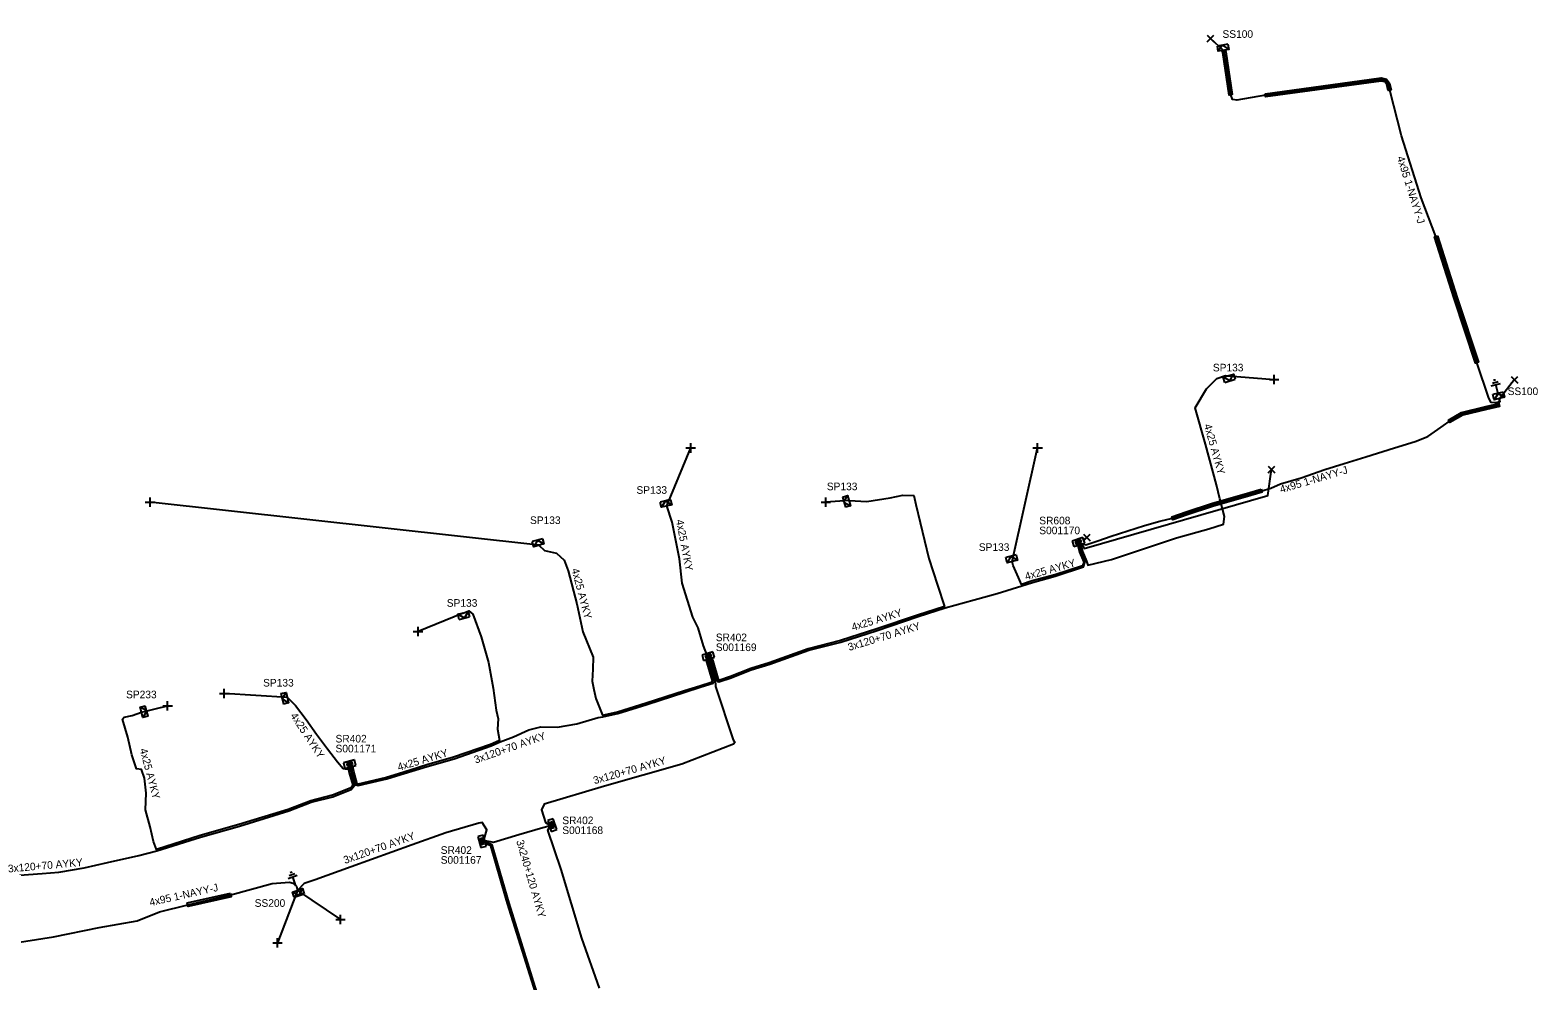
# Model space of a CAD drawing. Extents: x -763093 to -760976, y -1155572 to -1152009.
# Drawn here: x -761448.7 to -761250.7, y -1152363.9 to -1152239 of the extents above; entities that cross this region are included whole.
import ezdxf

# ---------------------------------------------------------------- set-up
doc = ezdxf.new("R2010")
doc.units = 0
for name, color, linetype in [('Vrstva 1', 7, 'Continuous'), ('Vrstva 14', 7, 'Continuous'), ('Vrstva 15', 7, 'Continuous'), ('Vrstva 20', 7, 'Continuous'), ('Vrstva 28', 7, 'Continuous'), ('Vrstva 29', 7, 'Continuous'), ('Vrstva 30', 7, 'Continuous'), ('Vrstva 31', 7, 'Continuous'), ('Vrstva 33', 7, 'Continuous'), ('Vrstva 34', 7, 'Continuous'), ('Vrstva 5', 7, 'Continuous'), ('Vrstva 59', 7, 'Continuous'), ('Vrstva 6', 7, 'Continuous'), ('Vrstva 8', 7, 'Continuous'), ('Vrstva 9', 7, 'Continuous')]:
    doc.layers.add(name, color=color, linetype=linetype)

# ---------------------------------------------------------------- blocks, each defined once
blk = doc.blocks.new('NN800')
at = {"layer": 'Vrstva 1'}
for points in [[(-0.44, 0.44), (0.44, -0.44)], [(-0.44, -0.44), (0.44, 0.44)]]:
    blk.add_lwpolyline(points, dxfattribs=at)
blk = doc.blocks.new('NN620')
at = {"layer": 'Vrstva 8'}
for points in [[(0.75, 0), (-0.75, 0)], [(-0.75, 0), (-0.75, -0.75)], [(0.75, -0.75), (0.75, 0)], [(-0.75, -0.75), (0.75, -0.75)], [(0.37, -0.18), (-0.38, -0.18)], [(-0.38, -0.18), (-0.38, -0.56)], [(-0.38, -0.56), (0.37, -0.56)], [(0.32, -0.23), (-0.33, -0.23)], [(-0.33, -0.23), (-0.33, -0.51)], [(-0.33, -0.51), (0.32, -0.51)], [(0.27, -0.27), (-0.28, -0.27)], [(-0.28, -0.27), (-0.28, -0.46)], [(-0.28, -0.46), (0.27, -0.46)], [(0.23, -0.32), (-0.23, -0.32)], [(-0.23, -0.32), (-0.23, -0.42)], [(-0.23, -0.42), (0.23, -0.42)], [(-0.19, -0.37), (0.19, -0.37)], [(0.23, -0.42), (0.23, -0.32)], [(0.27, -0.46), (0.27, -0.27)], [(0.32, -0.51), (0.32, -0.23)], [(0.37, -0.56), (0.37, -0.18)]]:
    blk.add_lwpolyline(points, dxfattribs=at)
blk = doc.blocks.new('NN630')
at = {"layer": 'Vrstva 9'}
for points in [[(0, -0.7), (-0.7, 0)], [(-0.7, -0.7), (-0.7, 0), (0.7, 0), (0.7, -0.7)], [(-0.7, -0.7), (0.7, -0.7)], [(0, -0.7), (0.7, 0)]]:
    blk.add_lwpolyline(points, dxfattribs=at)
blk = doc.blocks.new('NN810')
at = {"layer": 'Vrstva 14'}
for points in [[(0.63, -1.89), (-0.62, -1.89)], [(0, -0.64), (0, -1.89)], [(0.39, -2.2), (-0.4, -2.2)], [(0, -2.52), (-0.12, -2.52)], [(0.14, -2.52), (0, -2.52)]]:
    blk.add_lwpolyline(points, dxfattribs=at)

msp = doc.modelspace()

# ---------------------------------------------------------------- linework, layer by layer
at = {"layer": 'Vrstva 20'}
for points in [[(-761291.83, -1152241.57), (-761291.74, -1152241.82), (-761290.87, -1152247.46), (-761291.27, -1152247.52), (-761292.12, -1152241.92), (-761292.21, -1152241.71)], [(-761286.56, -1152247.35), (-761271.31, -1152245.27), (-761270.6, -1152245.43), (-761270.23, -1152245.96), (-761270.01, -1152246.81), (-761270.39, -1152246.91), (-761270.59, -1152246.14), (-761270.84, -1152245.79), (-761271.33, -1152245.67), (-761286.5, -1152247.75)], [(-761263.93, -1152266.03), (-761261.36, -1152274.14), (-761258.55, -1152282.6), (-761258.93, -1152282.72), (-761261.74, -1152274.26), (-761264.31, -1152266.15)], [(-761255.85, -1152288.05), (-761255.77, -1152288.45), (-761257.48, -1152288.83), (-761260.61, -1152289.58), (-761262.28, -1152290.55), (-761262.48, -1152290.21), (-761260.77, -1152289.2), (-761257.58, -1152288.45)], [(-761287.06, -1152299.3), (-761286.94, -1152299.68), (-761288.43, -1152300.12), (-761293.49, -1152301.57), (-761296.81, -1152302.65), (-761298.67, -1152303.31), (-761298.81, -1152302.93), (-761296.93, -1152302.27), (-761293.61, -1152301.19), (-761288.55, -1152299.74)], [(-761422.44, -1152352.36), (-761422.33, -1152352.84), (-761428.01, -1152354.12), (-761428.11, -1152353.64)]]:
    msp.add_lwpolyline(points, close=True, dxfattribs=at)
at = {"layer": 'Vrstva 5'}
for points in [[(-761255.79, -1152287.38), (-761255.77, -1152287.54), (-761255.75, -1152287.82), (-761256.36, -1152287.95), (-761256.87, -1152287.91), (-761257.18, -1152287.35), (-761258.74, -1152282.66), (-761261.55, -1152274.2), (-761264.12, -1152266.09), (-761266.07, -1152261.03), (-761268.63, -1152252.86), (-761270.2, -1152246.86), (-761270.41, -1152246.05), (-761270.72, -1152245.61), (-761271.32, -1152245.47), (-761286.53, -1152247.55), (-761290.28, -1152248.19), (-761290.86, -1152248.1), (-761291.07, -1152247.49), (-761291.93, -1152241.87), (-761292.02, -1152241.64)], [(-761310.78, -1152306.54), (-761310.56, -1152307.46), (-761310.01, -1152308.73), (-761309.83, -1152309.27), (-761306.73, -1152308.52), (-761300.15, -1152306.34), (-761298.2, -1152305.67), (-761293.96, -1152304.5), (-761292.04, -1152303.87), (-761291.91, -1152302.86), (-761292.49, -1152300.56), (-761292.94, -1152298.7), (-761294.39, -1152293.4), (-761295.74, -1152288.61), (-761294.24, -1152286.09), (-761292.9, -1152284.74), (-761291.75, -1152284.37), (-761291.38, -1152284.39)], [(-761310.47, -1152306.43), (-761310.12, -1152306.61), (-761308.54, -1152306.08), (-761306.77, -1152305.47), (-761302.39, -1152304.08), (-761300.39, -1152303.51), (-761298.74, -1152303.12), (-761296.87, -1152302.46), (-761293.55, -1152301.38), (-761288.49, -1152299.93), (-761287, -1152299.49), (-761285.83, -1152299.14), (-761284.53, -1152298.61), (-761281.84, -1152297.81), (-761278.73, -1152296.72), (-761276.18, -1152295.93), (-761273.33, -1152295.04), (-761269.56, -1152293.88), (-761266.84, -1152293.02), (-761265.18, -1152292.38), (-761263.87, -1152291.43), (-761262.38, -1152290.38), (-761260.69, -1152289.39), (-761257.53, -1152288.64), (-761255.81, -1152288.25), (-761255.79, -1152287.38)], [(-761341.2, -1152300.8), (-761338.88, -1152300.9), (-761335.82, -1152300.44), (-761334.13, -1152300.1), (-761332.68, -1152300.11), (-761332.41, -1152301.32), (-761330.71, -1152308.4), (-761329.6, -1152311.91), (-761328.66, -1152314.71), (-761332.2, -1152315.85), (-761337.55, -1152317.66), (-761342.33, -1152319.17), (-761346.56, -1152320.26), (-761351.68, -1152322.1), (-761354.1, -1152322.86), (-761356.75, -1152323.91), (-761358.32, -1152324.41), (-761359.06, -1152321.83), (-761359.21, -1152321.45)], [(-761359.89, -1152320.99), (-761360.32, -1152319.86), (-761361, -1152317.5), (-761361.71, -1152316.09), (-761363.12, -1152311.66), (-761363.46, -1152308.43), (-761364.44, -1152303.61), (-761365.14, -1152301.5)], [(-761381.94, -1152306.66), (-761381.21, -1152307.36), (-761379.64, -1152307.7), (-761378.61, -1152308.62), (-761378.09, -1152310.04), (-761376.96, -1152314.37), (-761376.15, -1152318.03), (-761374.8, -1152321.38), (-761374.86, -1152322.92), (-761374.93, -1152324.53), (-761374.74, -1152325.63), (-761374.45, -1152326.8), (-761373.59, -1152328.99), (-761371.6, -1152328.56), (-761367.83, -1152327.38), (-761362.82, -1152325.75), (-761360.82, -1152325.11), (-761359.2, -1152324.6), (-761359.13, -1152324.47), (-761359.82, -1152322.09), (-761359.95, -1152321.73)], [(-761359.39, -1152321.52), (-761359.25, -1152321.9), (-761358.48, -1152324.57), (-761358.31, -1152324.62), (-761356.69, -1152324.09), (-761354.04, -1152323.04), (-761351.62, -1152322.29), (-761346.5, -1152320.46), (-761342.27, -1152319.37), (-761337.49, -1152317.84), (-761332.14, -1152316.04), (-761328.6, -1152314.9), (-761324.75, -1152313.83), (-761321.73, -1152312.99), (-761318.49, -1152312.01), (-761317.09, -1152311.55), (-761314.13, -1152310.74), (-761310.4, -1152309.51), (-761310.19, -1152308.81), (-761310.75, -1152307.52), (-761310.97, -1152306.6)], [(-761311.17, -1152306.65), (-761310.94, -1152307.58), (-761310.37, -1152308.89), (-761310.54, -1152309.35), (-761314.19, -1152310.54), (-761317.15, -1152311.35), (-761318.56, -1152311.82), (-761318.93, -1152310.9), (-761319.63, -1152309.31), (-761319.76, -1152308.78)], [(-761391.89, -1152315.56), (-761391.13, -1152315.27), (-761390.59, -1152315.71), (-761389.5, -1152318.67), (-761388.54, -1152322.07), (-761387.92, -1152325.45), (-761387.56, -1152328.31), (-761387.29, -1152329.46), (-761387.39, -1152330.81), (-761387.1, -1152332.3), (-761388.3, -1152332.85), (-761393.14, -1152334.52), (-761396.65, -1152335.51), (-761399.68, -1152336.47), (-761401.95, -1152337.16), (-761405.66, -1152338.04), (-761405.82, -1152337.99), (-761406.25, -1152336.4), (-761406.39, -1152335.69)], [(-761406.58, -1152335.75), (-761406.44, -1152336.45), (-761405.99, -1152338.15), (-761405.66, -1152338.24), (-761401.89, -1152337.36), (-761399.62, -1152336.66), (-761396.59, -1152335.71), (-761393.08, -1152334.71), (-761388.22, -1152333.03), (-761387.04, -1152332.49), (-761385.26, -1152331.81), (-761383.26, -1152330.92), (-761381.67, -1152330.52), (-761379.47, -1152330.55), (-761376.93, -1152330.12), (-761374.15, -1152329.28), (-761373.53, -1152329.18), (-761371.56, -1152328.76), (-761367.77, -1152327.56), (-761362.76, -1152325.94), (-761360.76, -1152325.3), (-761359.05, -1152324.77), (-761358.89, -1152324.58), (-761359.63, -1152322.02), (-761359.77, -1152321.66)], [(-761359.58, -1152321.59), (-761359.44, -1152321.96), (-761358.77, -1152324.28), (-761358.76, -1152325.22), (-761356.41, -1152332.22), (-761356.21, -1152332.58), (-761356.37, -1152332.81), (-761363.16, -1152335.41), (-761373.34, -1152338.32), (-761381.24, -1152340.66), (-761381.6, -1152341.43), (-761381.05, -1152343.08), (-761380.61, -1152343.34)], [(-761414.97, -1152326.68), (-761413.92, -1152327.7), (-761412.48, -1152329.54), (-761411.16, -1152331.46), (-761409.69, -1152333.39), (-761408.39, -1152335.1), (-761407.66, -1152335.98), (-761407.13, -1152336.09), (-761407.17, -1152335.91)], [(-761406.97, -1152335.87), (-761406.83, -1152336.54), (-761406.39, -1152338.18), (-761406.7, -1152338.59), (-761409.06, -1152339.5), (-761411.9, -1152340.22), (-761414.85, -1152341.38), (-761421.32, -1152343.35), (-761426.42, -1152344.79), (-761432.15, -1152346.62), (-761432.53, -1152345.57), (-761432.99, -1152343.67), (-761433.6, -1152341.4), (-761433.53, -1152339.23), (-761433.73, -1152337.26), (-761434.13, -1152336.13), (-761434.77, -1152336.02), (-761435.4, -1152334.2), (-761435.94, -1152331.87), (-761436.62, -1152329.49), (-761436.41, -1152329.23), (-761435.37, -1152329.02), (-761434.12, -1152328.6)], [(-761450.14, -1152349.98), (-761447.16, -1152349.78), (-761445, -1152349.59), (-761441.65, -1152349.04), (-761438.6, -1152348.33), (-761434.47, -1152347.42), (-761432.09, -1152346.8), (-761426.36, -1152344.99), (-761421.26, -1152343.55), (-761414.79, -1152341.56), (-761411.84, -1152340.41), (-761409, -1152339.69), (-761406.58, -1152338.75), (-761406.17, -1152338.22), (-761406.64, -1152336.49), (-761406.78, -1152335.81)], [(-761389.11, -1152345.26), (-761388.78, -1152344.03), (-761389.4, -1152343.08), (-761389.83, -1152343.15), (-761394.15, -1152344.46), (-761398.56, -1152346.01), (-761406.6, -1152348.9), (-761411.32, -1152350.6), (-761412.74, -1152351.09), (-761413.65, -1152352)], [(-761389.04, -1152345.45), (-761387.89, -1152345.67), (-761384.57, -1152344.65), (-761381.43, -1152343.76), (-761380.57, -1152343.5)], [(-761373.98, -1152364.86), (-761376.31, -1152358.28), (-761379, -1152349.26), (-761380.75, -1152344.09), (-761380.51, -1152343.63)], [(-761382.2, -1152365.35), (-761385.85, -1152353.67), (-761386.07, -1152352.92), (-761388.07, -1152346.03), (-761388.99, -1152345.64)], [(-761382.4, -1152365.41), (-761386.05, -1152353.73), (-761386.27, -1152352.98), (-761388.25, -1152346.15), (-761388.93, -1152345.85)], [(-761451.55, -1152359.02), (-761445.67, -1152358.12), (-761439.7, -1152356.89), (-761434.68, -1152356), (-761431.74, -1152354.83), (-761428.06, -1152353.88), (-761422.38, -1152352.6), (-761416.97, -1152351.1), (-761414.67, -1152350.93), (-761414.2, -1152351.06), (-761413.77, -1152351.45), (-761413.65, -1152352)]]:
    msp.add_lwpolyline(points, dxfattribs=at)
at = {"layer": 'Vrstva 59'}
for points in [[(-761292.02, -1152241.64), (-761293.75, -1152240.09)], [(-761291.38, -1152284.39), (-761285.38, -1152284.88)], [(-761255.79, -1152287.38), (-761253.79, -1152284.85)], [(-761365.14, -1152301.5), (-761362, -1152293.88)], [(-761319.76, -1152308.78), (-761316.44, -1152293.88)], [(-761310.62, -1152306.47), (-761310.31, -1152307.07), (-761286.21, -1152300.14), (-761285.72, -1152296.71)], [(-761381.94, -1152306.66), (-761433, -1152301)], [(-761341.2, -1152300.8), (-761344.25, -1152301)], [(-761310.44, -1152306.05), (-761309.97, -1152305.64)], [(-761391.89, -1152315.56), (-761397.81, -1152318)], [(-761434.12, -1152328.6), (-761430.69, -1152327.75)], [(-761414.97, -1152326.68), (-761423.25, -1152326.13)], [(-761413.65, -1152352), (-761416.27, -1152358.88)], [(-761413.65, -1152352), (-761407.99, -1152355.82)]]:
    msp.add_lwpolyline(points, dxfattribs=at)

# ---------------------------------------------------------------- block references
at = {"layer": 'Vrstva 15'}
for p, rotation in [((-761255.79, -1152287.38), -165.6506679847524), ((-761413.65, -1152352), -160.96196117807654)]:
    msp.add_blockref('NN810', p, dxfattribs=dict(at, rotation=rotation))
at = {"layer": 'Vrstva 28'}
for p, rotation in [((-761310.97, -1152306.6), -162.03284333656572), ((-761359.58, -1152321.59), -163.52304707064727), ((-761406.68, -1152335.78), -165.110952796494), ((-761380.54, -1152343.54), 108.43495001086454), ((-761389.04, -1152345.45), -73.82321948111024)]:
    msp.add_blockref('NN620', p, dxfattribs=dict(at, rotation=rotation))
at = {"layer": 'Vrstva 31'}
for p, rotation in [((-761292.02, -1152241.64), -169.9193805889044), ((-761291.38, -1152284.39), 16.752011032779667), ((-761255.79, -1152287.38), -165.65066813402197), ((-761341.2, -1152300.8), -73.3976761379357), ((-761365.14, -1152301.5), -165.68094724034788), ((-761381.94, -1152306.66), -164.5675805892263), ((-761319.76, -1152308.78), -164.89636388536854), ((-761391.89, -1152315.56), 13.829566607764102), ((-761434.12, -1152328.6), 105.0026083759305), ((-761414.97, -1152326.68), -77.00356945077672), ((-761413.65, -1152352), 19.038038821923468)]:
    msp.add_blockref('NN630', p, dxfattribs=dict(at, rotation=rotation))
at = {"layer": 'Vrstva 34'}
for p in [(-761293.75, -1152240.09), (-761253.81, -1152284.93), (-761285.72, -1152296.71), (-761309.97, -1152305.64)]:
    msp.add_blockref('NN800', p, dxfattribs=at)
for p, rotation in [((-761285.38, -1152284.88), 45), ((-761362, -1152293.88), 45), ((-761316.44, -1152293.88), 44.99999995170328), ((-761433, -1152301), 45), ((-761344.25, -1152301), 45), ((-761397.81, -1152318), 45), ((-761423.25, -1152326.13), 45), ((-761430.69, -1152327.75), 44.99999995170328), ((-761407.99, -1152355.82), 45), ((-761416.27, -1152358.88), 45)]:
    msp.add_blockref('NN800', p, dxfattribs=dict(at, rotation=rotation))

# ---------------------------------------------------------------- texts
at = {"layer": 'Vrstva 29'}
for s, p in [('S001170', (-761316.22, -1152305.21)), ('S001169', (-761358.7, -1152320.56)), ('S001171', (-761408.64, -1152333.87)), ('S001168', (-761378.86, -1152344.6)), ('S001167', (-761394.83, -1152348.5))]:
    msp.add_text(s, height=1, dxfattribs=at).set_placement(p)
at = {"layer": 'Vrstva 30'}
for s, p in [('SR608', (-761316.22, -1152303.91)), ('SR402', (-761358.7, -1152319.26)), ('SR402', (-761408.64, -1152332.57)), ('SR402', (-761378.86, -1152343.3)), ('SR402', (-761394.83, -1152347.2))]:
    msp.add_text(s, height=1, dxfattribs=at).set_placement(p)
at = {"layer": 'Vrstva 33'}
for s, p in [('SS100', (-761292.16, -1152240)), ('SP133', (-761293.42, -1152283.82)), ('SS100', (-761254.71, -1152286.93)), ('SP133', (-761369.12, -1152299.9)), ('SP133', (-761344.12, -1152299.43)), ('SP133', (-761383.1, -1152303.87)), ('SP133', (-761324.16, -1152307.4)), ('SP133', (-761394.03, -1152314.74)), ('SP233', (-761436.15, -1152326.76)), ('SP133', (-761418.15, -1152325.22)), ('SS200', (-761419.26, -1152354.16))]:
    msp.add_text(s, height=1, dxfattribs=at).set_placement(p)
at = {"layer": 'Vrstva 6'}
for s, rotation, p in [('4x95 1-NAYY-J', 287.398, (-761269.26, -1152255.72)), ('4x25 AYKY', 285.7, (-761294.6, -1152290.87)), ('4x95 1-NAYY-J', 16.562, (-761284.46, -1152299.81)), ('4x25 AYKY', 280.899, (-761363.94, -1152303.38)), ('4x25 AYKY', 284.791, (-761377.66, -1152309.82)), ('4x25 AYKY', 15.783, (-761317.95, -1152311.25)), ('4x25 AYKY', 16.93, (-761340.7, -1152317.92)), ('3x120+70 AYKY', 16.966, (-761341.18, -1152320.55)), ('4x25 AYKY', 303.553, (-761414.63, -1152329.06)), ('3x120+70 AYKY', 19.25, (-761390.24, -1152335.35)), ('4x25 AYKY', 284.797, (-761434.37, -1152333.48)), ('4x25 AYKY', 16.612, (-761400.34, -1152336.31)), ('3x120+70 AYKY', 15.953, (-761374.63, -1152338.06)), ('3x120+70 AYKY', 19.628, (-761407.39, -1152348.54)), ('3x240+120 AYKY', 286.244, (-761384.92, -1152345.52)), ('3x120+70 AYKY', 5.074, (-761451.62, -1152349.65)), ('4x95 1-NAYY-J', 12.7, (-761432.97, -1152354.08))]:
    msp.add_text(s, height=1, rotation=rotation, dxfattribs=at).set_placement(p)

doc.saveas('drawing.dxf')
